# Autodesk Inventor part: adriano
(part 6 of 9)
sketch "スケッチ151"
  geometry: L1 (25.154, 31.686)-(59.588, 31.686) reference; L2 (11.954, 9.686)-(25.154, 31.686) reference; L3 (12.588, 9.686)-(12.588, -19.314) reference; L4 (55.588, -38.314)-(55.588, -23.314) reference; L5 (113.588, -38.314)-(55.588, -38.314) reference; L6 (82.588, 31.686)-(112.588, 31.686) reference; L7 (59.088, -12.814)-(28.088, -12.814) reference; L8 (28.088, -12.814)-(28.088, 12.186) reference; L9 (28.088, 12.186)-(59.088, 12.186) reference; L10 (59.088, 12.186)-(59.088, 25.686) reference; L11 (103.588, 31.686)-(103.588, 2.186); L12 (103.588, 2.186)-(99.588, 2.186); L13 (89.588, 12.186)-(89.588, 24.869); L14 (89.588, 24.869)-(81.529, 24.869); L15 (83.588, 31.686)-(103.588, 31.686); L16 (103.588, -38.314)-(103.588, -1.814); L17 (103.588, -1.814)-(99.588, -1.814); L18 (89.588, -11.814)-(89.588, -26.444); L19 (89.588, -26.444)-(58.713, -26.444); L20 (58.713, -26.444)-(58.713, -14.154); L21 (58.713, -14.154)-(26.588, -14.154); L22 (26.588, -14.154)-(26.588, -8.314); L23 (26.588, -8.314)-(12.588, -8.314); L24 (12.588, -8.314)-(12.588, -23.314); L25 (12.588, -23.314)-(55.588, -23.314); L26 (55.588, -23.314)-(55.588, -38.314); L27 (55.588, -38.314)-(103.588, -38.314); L28 (12.588, -2.229)-(26.588, -2.229); L29 (26.588, -2.229)-(26.588, 13.103); L30 (26.588, 13.103)-(58.238, 13.103); L31 (58.238, 13.103)-(58.238, 31.686); L32 (58.238, 31.686)-(25.154, 31.686); L33 (25.154, 31.686)-(12.588, 10.743); L34 (12.588, 10.743)-(12.588, -2.229); L35 (103.588, 31.686)-(83.588, 31.686); L36 (83.588, 31.686)-(83.588, 24.869); L37 (113.588, -18.314)-(113.588, -38.314) reference; A1 r 10 centre (89.588, 2.186) between (99.588, 2.186) and (89.588, 12.186); A2 r 10 centre (89.588, -1.814) between (89.588, -11.814) and (99.588, -1.814); 1 further point
  constraints: 52 end point, 19 perpendicular, 7 point on line, 4 parallel, 4 point on circle, 2 centre point, 1 collinear
  dimensions: "d2968" = 4 distance between parallel lines of L17 L12; "d2970" = 14 distance between parallel lines of L11 L13; "d2971" = 0 distance between parallel lines of L16 L11; "d2972" = 4 distance of L11.end L12.end; "d2974" = 0 horizontal distance of L17.end L12.end; "d2975" = 0 distance from line of L13 A1.centre; "d2976" = 0 distance from line of L18 A2.centre; "d2977" = 0 distance between parallel lines of L18 L13; "d2978" = 0 distance from line of L17 A2.centre; "d2979" = 29.5 distance between parallel lines of L6 L12; "d2980" = 0 distance between parallel lines of L22 L29; "d2981" = 0 distance from line of L1 L31.end; "d2982" = 14 distance between parallel lines of L22 L3; "d4362" = 10 distance between parallel lines of L37 L16
extrude "garden" join sketch "スケッチ151" distance "d2983" = 0.5; taper "d2984" = 0 deg
sketch "スケッチ158"
  geometry: L1 (-16.412, -4.314)-(-2.412, -4.314) reference; L2 (7.588, -8.314)-(6.588, -8.314) reference; L3 (7.588, -2.314)-(7.588, 9.686) reference; L4 (-19.412, 9.686)-(7.588, 9.686) reference; L5 (-19.412, -18.314)-(-19.412, 9.686) reference; L6 (7.588, -18.314)-(-19.412, -18.314) reference; L7 (-12.588, 9.686)-(7.588, 9.686); L8 (7.588, 9.686)-(7.588, 7.686); L9 (7.588, 7.686)-(-12.588, 7.686); L10 (-12.588, 7.686)-(-12.588, 9.686); L11 (-19.412, 4.686)-(0, 4.686); L12 (0, 4.686)-(0, 1.686); L13 (0, 1.686)-(-19.412, 1.686); L14 (-19.412, 1.686)-(-19.412, 4.686); L15 (0, 4.686)-(2, 4.686); L16 (2, 4.686)-(2, -4.314); L17 (2, -4.314)-(0, -4.314); L18 (0, -4.314)-(0, 4.686); L19 (-19.412, -16.314)-(7.588, -16.314); L20 (7.588, -16.314)-(7.588, -18.314); L21 (7.588, -18.314)-(-19.412, -18.314); L22 (-19.412, -18.314)-(-19.412, -16.314); L23 (0, -8.314)-(7.588, -8.314); L24 (7.588, -8.314)-(7.588, -16.314); L25 (7.588, -16.314)-(0, -16.314); L26 (0, -16.314)-(0, -8.314); C1 r 1 at (5.588, -14.314) reference; 1 further point
  constraints: 40 end point, 10 parallel, 5 horizontal, 5 perpendicular, 4 point on line
  dimensions: "d3045" = 2 distance of L11.end L15.end; "d3047" = 2 distance of L9.end L7.start; "d3048" = 3 distance between parallel lines of L11 L9; "d3049" = 3 distance between parallel lines of L13 L11; "d3050" = 0 distance between parallel lines of L17 L1; "d3051" = 2 distance between parallel lines of L6 L19; "d3052" = 0 distance between parallel lines of L2 L23
extrude "押し出し148" join sketch "スケッチ158" distance "d3053" = 0.5; taper "d3054" = 0 deg
sketch "スケッチ159"
  geometry: L1 (0, 0)-(21, 0) reference; L2 (-0.5, 0)-(9.75, 0); L3 (9.75, 0)-(9.75, 20); L4 (9.75, 20)-(-0.5, 0); L5 (21.5, 0)-(9.75, 0); L6 (9.75, 0)-(9.75, 20); L7 (9.75, 20)-(21.5, 0); 1 further point
  constraints: 12 end point, 2 perpendicular, 2 point on line
  dimensions: "d3055" = 0 distance of L6.end L3.end; "d3057" = 0 distance of L3.end L6.end; "d3058" = 0.5 distance of L5.start L1.end; "d3059" = 0.5 distance of L1.start L2.start; "d3060" = 20 distance of L2.end L3.end
extrude "redroof" join sketch "スケッチ159" distance "d3061" = 48.5; taper "d3062" = 0 deg
sketch "スケッチ160"
  geometry: L1 (-9.75, 20)-(0.5, 0) reference; L2 (0, 0)-(-21, 0) reference; L3 (-21.5, 0)-(-9.75, 20); L4 (-9.75, 20)-(0.5, 0); L5 (0.5, 0)-(-21.5, 0); 1 further point
  constraints: 6 end point, 2 collinear
extrude "押し出し150" join sketch "スケッチ160" distance "d3063" = 0.5; taper "d3064" = 0 deg
sketch "スケッチ161"
  geometry: L1 (0, 0)-(22, 0) reference; L2 (-0.1, 0)-(10.5, 0); L3 (11, 0)-(11, 20); L4 (11, 20)-(-0.1, 0); L5 (22.1, 0)-(11, 0); L6 (11, 0)-(11, 20); L7 (11, 20)-(22.1, 0); 3 further points
  constraints: 12 end point, 2 midpoint, 2 perpendicular, 1 point on line
  dimensions: "d3065" = 0 distance of L6.end L3.end; "d3067" = 1.9 distance of point (-2, 0) L2.start; "d3068" = 1.9 distance of point (24, 0) L5.start; "d3069" = 20 distance from line of L1 L3.end
extrude "押し出し151" join sketch "スケッチ161" distance "d3070" = 52; taper "d3071" = 0 deg
sketch "スケッチ162"
  geometry: L1 (-11, 20)-(0.1, 0) reference; L2 (-22.1, 0)-(-11, 20) reference; L3 (0, 0)-(-22, 0) reference; L4 (-11, 20)-(-22.1, 0); L5 (-22.1, 0)-(0.1, 0); L6 (0.1, 0)-(-11, 20); 1 further point
  constraints: 6 end point, 3 collinear
extrude "押し出し152" join sketch "スケッチ162" distance "d3072" = 0.5; taper "d3073" = 0 deg
sketch "スケッチ163"
  geometry: L1 (0, 0)-(52, 0) reference; L2 (18, -1.6)-(18, -17.464) reference; L3 (34, -17.464)-(34, -1.6) reference; L4 (15.5, 0)-(36.5, 0); L5 (36.5, 0)-(36.5, 20); L6 (36.5, 20)-(15.5, 20); L7 (15.5, 20)-(15.5, 0); 1 further point
  constraints: 8 end point, 2 parallel, 1 horizontal, 1 perpendicular, 1 point on line
  dimensions: "d3074" = 2.5 distance between parallel lines of L2 L7; "d3075" = 2.5 distance between parallel lines of L5 L3; "d3076" = 20 distance between parallel lines of L1 L6
extrude "押し出し153" join sketch "スケッチ163" distance "d3077" = 2; taper "d3078" = 0 deg
sketch "スケッチ164"
  geometry: L1 (18.5, 17.464)-(18.5, 37.464) reference; L2 (-2.5, 37.464)-(-2.5, 17.464) reference; L3 (-18, 17.464)-(-2.5, 17.464) reference; L4 (16, 0)-(16, 15.864) reference; L5 (1.883, 32.964)-(3.483, 32.964); L6 (14.117, 32.964)-(12.517, 32.964); L7 (18.576, 18.464)-(29.7, 26.964); L8 (29.7, 26.964)-(15.7, 26.964); L9 (-2.576, 18.464)-(-13.7, 26.964); L10 (-13.7, 26.964)-(0.3, 26.964); L11 (0.3, 26.964)-(-13.7, 26.964); L12 (-13.7, 26.964)-(-2.7, 30.964); L13 (-2.7, 30.964)-(1.883, 32.964); L14 (18.7, 30.964)-(14.117, 32.964); L15 (18.7, 30.964)-(29.7, 26.964); L16 (29.7, 26.964)-(15.7, 26.964); L17 (-2.7, 30.964)-(-2.7, 38.962); L18 (-2.7, 38.962)-(1.883, 32.964); L19 (14.117, 32.964)-(18.7, 38.962); L20 (18.7, 38.962)-(18.7, 30.964); L21 (-2.7, 38.962)-(18.7, 38.962); L22 (-2.7, 38.962)-(1.883, 32.964); L23 (1.883, 32.964)-(3.483, 32.964); L24 (12.517, 32.964)-(14.117, 32.964); L25 (14.117, 32.964)-(18.7, 38.962); A1 r 14 centre (-13.7, 26.964) between (-2.576, 18.464) and (0.3, 26.964); A2 r 14 centre (29.7, 26.964) between (15.7, 26.964) and (18.576, 18.464); A3 r 5 centre (-2.7, 30.964) between (0.3, 26.964) and (1.883, 32.964); A4 r 5 centre (18.7, 30.964) between (14.117, 32.964) and (15.7, 26.964); A5 r 4.517 centre (8, 32.964) between (12.517, 32.964) and (3.483, 32.964); 1 further point
  constraints: 42 end point, 11 point on circle, 5 centre point, 5 collinear, 3 perpendicular, 2 parallel
  dimensions: "d3085" = 14 distance of L10.end L9.end; "d3087" = 14 distance of L7.end L8.end; "d3088" = 2.8 distance from line of L10.end L2; "d3089" = 2.8 distance from line of L1 L8.end; "d3090" = 11 horizontal distance of L12.end L9.end; "d3091" = 11 horizontal distance of L7.end L14.start; "d3092" = 9.5 distance from line of L3 L9.end; "d3093" = 0 vertical distance of L7.end L9.end; "d3094" = 0 vertical distance of L14.start L12.end; "d3095" = 0 vertical distance of L10.end L9.end; "d3096" = 0 vertical distance of L7.end L8.end; "d3097" = 4 vertical distance of L10.end L12.end; "d3098" = 1 distance from line of L3 L9.start; "d3099" = 0 vertical distance of L7.start L9.start; "d3100" = 1.6 distance of L5.start L5.end; "d3101" = 1.6 distance of L6.start L6.end; "d3102" = 0 distance of L6.end L24.start; "d3103" = 2 distance from line of L12.end L5; "d3104" = 0 distance between parallel lines of L6 L5; "d3105" = 0 distance from line of L6 A5.centre
extrude "押し出し154" cut sketch "スケッチ164" distance "d3106" = 2; taper "d3107" = 0 deg
sketch "スケッチ165"
  geometry: L1 (3.483, 32.964)-(1.883, 32.964) reference; L2 (-2.5, 18.564)-(-2.5, 17.464) reference; L3 (-18, 15.864)-(0, 15.864) reference; L4 (16, 15.864)-(34, 15.864) reference; L5 (14.117, 32.964)-(12.517, 32.964) reference; L6 (8.396, 37.464)-(7.604, 37.464) reference; L7 (2.885, 32.164)-(4.2, 32.164); L8 (4.2, 32.164)-(4.2, 32.964); L9 (11.8, 32.164)-(11.8, 32.964); L10 (-1.7, 18.564)-(-1.7, 15.864); L11 (-1.7, 15.864)-(-2.5, 15.864); L12 (-2.5, 15.864)-(-2.5, 18.564); L13 (17.7, 18.564)-(17.7, 15.864); L14 (17.7, 15.864)-(18.5, 15.864); L15 (18.5, 15.864)-(18.5, 18.564); L16 (1.883, 32.964)-(3.483, 32.964); L17 (12.517, 32.964)-(14.117, 32.964); L18 (-2.5, 18.564)-(-1.7, 18.564); L19 (17.7, 18.564)-(18.5, 18.564); L20 (0.3, 26.964)-(0.942, 26.564); L21 (2.885, 32.164)-(1.883, 32.964); L22 (11.8, 32.164)-(13.123, 32.164); A1 r 4.517 centre (8, 32.964) between (7.604, 37.464) and (3.483, 32.964) reference; A2 r 5 centre (-2.7, 30.964) between (0.3, 26.964) and (1.883, 32.964) reference; A3 r 14 centre (-13.7, 26.964) between (-2.5, 18.564) and (0.3, 26.964) reference; A4 r 14 centre (29.7, 26.964) between (15.7, 26.964) and (18.5, 18.564) reference; A5 r 5 centre (18.7, 30.964) between (14.117, 32.964) and (15.7, 26.964) reference; A6 r 4.517 centre (8, 32.964) between (12.517, 32.964) and (8.396, 37.464) reference; A7 r 14 centre (-13.7, 26.964) between (-2.5, 18.564) and (0.3, 26.964); A8 r 5 centre (-2.7, 30.964) between (0.3, 26.964) and (1.883, 32.964); A9 r 5 centre (18.7, 30.964) between (14.117, 32.964) and (15.7, 26.964); A10 r 14 centre (29.7, 26.964) between (15.7, 26.964) and (18.5, 18.564); A11 r 4.517 centre (8, 32.964) between (12.517, 32.964) and (3.483, 32.964); A12 r 3.8 centre (8, 32.964) between (11.8, 32.964) and (4.2, 32.964); A13 r 5.712 centre (-2.7, 30.964) between (0.942, 26.564) and (2.885, 32.164); A14 r 14.648 centre (-13.7, 26.964) between (-1.7, 18.564) and (0.942, 26.564); A15 r 14.648 centre (29.7, 26.964) between (15.057, 26.574) and (17.7, 18.564); A16 r 5.705 centre (18.7, 30.964) between (13.123, 32.164) and (15.057, 26.574); 1 further point
  constraints: 32 end point, 20 point on circle, 10 centre point, 10 coincident, 6 perpendicular, 5 point on line, 3 parallel, 2 tangent, 1 collinear
  dimensions: "d3110" = 0 vertical distance of L13.start L10.start; "d3111" = 0 vertical distance of L9.start L7.end; "d3112" = 0.8 distance between parallel lines of L10 L12; "d3113" = 0.8 distance between parallel lines of L15 L13; "d3117" = 8 distance from line of L18 L20.end; "d3118" = 5.6 distance from line of L20.end L7; "d3119" = 7.6 distance between parallel lines of L9 L8
extrude "押し出し155" join sketch "スケッチ165" distance "d3122" = 0.5; taper "d3123" = 0 deg
sketch "スケッチ166"
  geometry: L1 (0, 15.864)-(0, 0) reference; L2 (0, 0)-(-18, 0) reference; L3 (0, -1.6)-(0, -16.536) reference; L4 (16, -16.536)-(0, -16.536) reference; L5 (16, -16.536)-(16, -1.6) reference; L6 (16, 0)-(16, 15.864) reference; L7 (16, 15.864)-(17.7, 15.864) reference; L8 (6, 24.464)-(6, 18.464); L9 (6, 18.464)-(10, 18.464); L10 (10, 18.464)-(10, 24.464); L11 (5, 11)-(5, 2); L12 (5, 2)-(11, 2); L13 (11, 2)-(11, 11); L14 (3, -7.536)-(3, -16.536); L15 (3, -16.536)-(13, -16.536); L16 (13, -16.536)-(13, -7.536); L17 (-18, 17.464)-(-2.5, 17.464) reference; C1 r 2.024 at (8, 32.964); A1 r 3.8 centre (8, 32.964) between (11.8, 32.964) and (4.2, 32.964) reference; A2 r 2 centre (8, 24.464) between (8, 26.464) and (6, 24.464); A3 r 2 centre (8, 24.464) between (10, 24.464) and (8, 26.464); A4 r 3 centre (8, 11) between (11, 11) and (5, 11); A5 r 5 centre (8, -7.536) between (13, -7.536) and (3, -7.536); 1 further point
  constraints: 18 end point, 8 point on circle, 5 centre point, 5 perpendicular, 4 parallel, 4 tangent, 2 coincident
  dimensions: "d3126" = 3 distance between parallel lines of L3 L14; "d3127" = 3 distance between parallel lines of L5 L16; "d3128" = 0 distance between parallel lines of L4 L15; "d3129" = 9 distance from line of L15 A5.centre; "d3130" = 2 distance between parallel lines of L2 L12; "d3131" = 5 distance between parallel lines of L1 L11; "d3132" = 5 distance between parallel lines of L6 L13; "d3133" = 9 distance from line of L12 A4.centre; "d3134" = 0 vertical distance of L13.end A4.centre; "d3135" = 1 distance between parallel lines of L17 L9; "d3136" = 6 distance from line of L9 A3.centre; "d3137" = 6 distance between parallel lines of L1 L8; "d3138" = 6 distance between parallel lines of L6 L10; "d3139" = 4 distance of L8.end L9.end (derived)
extrude "押し出し156" cut sketch "スケッチ166" distance "d3140" = 0.5; taper "d3141" = 0 deg
sketch "スケッチ167"
  geometry: L1 (0, 1.6)-(15.5, 1.6) reference; L2 (0, 0)-(15.5, 0) reference; L3 (1.5, 1.6)-(1.5, 21.6); L4 (1.5, 21.6)-(12.5, 21.6); L5 (1.5, 1.6)-(12.5, 21.6); L6 (39.5, 21.6)-(50.5, 21.6); L7 (50.5, 21.6)-(50.5, 1.929); L8 (50.5, 1.929)-(39.5, 21.6); L9 (1.5, 1.6)-(1.5, 21.6) reference; L10 (50.5, 21.6)-(50.5, 1.6) reference; L11 (1.5, 21.6)-(26, 21.6) reference; 1 further point
  constraints: 12 end point, 3 perpendicular, 1 collinear
  dimensions: "d3142" = 11 distance of L3.end L4.end; "d3144" = 11 distance of L6.start L6.end; "d3145" = 0 distance between parallel lines of L9 L3; "d3146" = 0 distance between parallel lines of L10 L7; "d3147" = 0 distance from line of L1 L3.start; "d3148" = 0 distance between parallel lines of L11 L4; "d3149" = 0 distance between parallel lines of L6 L4
extrude "押し出し157" cut sketch "スケッチ167" distance "d3150" = 28; taper "d3151" = 0 deg
sketch "スケッチ168"
  geometry: L1 (0, 0)-(31, 0) reference; L2 (0, -1.6)-(0, 0) reference; L3 (1.5, 0)-(1.5, 20); L4 (1.5, 20)-(12.5, 20); L5 (12.5, 20)-(1.5, 0); L6 (1.5, 0)-(1.5, 20) reference; L7 (1.5, 20)-(44.25, 20) reference; 1 further point
  constraints: 6 end point, 1 parallel, 1 perpendicular, 1 point on line
  dimensions: "d3152" = 11 distance of L3.end L4.end; "d3156" = 0 distance between parallel lines of L6 L3; "d3157" = 0 distance between parallel lines of L7 L4
extrude "押し出し158" cut sketch "スケッチ168" distance "d3154" = 28; taper "d3155" = 0 deg
sketch "スケッチ169"
  geometry: L1 (60.088, -11.414)-(29.088, -11.414) reference; L2 (29.088, 10.786)-(60.088, 10.786) reference; L3 (60.088, 10.786)-(60.088, 24.186) reference; L4 (69.588, 1.786)-(73.788, 1.786); L5 (73.788, 1.786)-(73.788, -2.414); L6 (73.788, -2.414)-(69.588, -2.414); L7 (69.588, -2.414)-(69.588, 1.786); 1 further point
  constraints: 8 end point, 2 parallel, 1 horizontal, 1 perpendicular
  dimensions: "d3158" = 9 distance between parallel lines of L2 L4; "d3159" = 9 distance between parallel lines of L1 L6; "d3162" = 4.2 distance of L4.start L4.end; "d3163" = 9.5 distance between parallel lines of L7 L3
extrude "top" join sketch "スケッチ169" distance "d3164" = 21; taper "d3165" = 0 deg
sketch "スケッチ170"
  geometry: L1 (73.788, 1.786)-(69.588, 1.786) reference; L2 (69.588, 1.786)-(69.588, -2.414) reference; L3 (69.588, -2.414)-(73.788, -2.414) reference; L4 (73.788, -2.414)-(73.788, 1.786) reference; L5 (70.388, 0.986)-(70.388, -1.614); L6 (70.388, -1.614)-(72.988, -1.614); L7 (72.988, -1.614)-(72.988, 0.986); L8 (72.988, 0.986)-(70.388, 0.986); L9 (70.988, 0.386)-(70.988, -1.014); L10 (70.988, -1.014)-(72.388, -1.014); L11 (72.388, -1.014)-(72.388, 0.386); L12 (72.388, 0.386)-(70.988, 0.386); 1 further point
  constraints: 16 end point, 4 parallel, 4 perpendicular
  dimensions: "d3166" = 0.8 distance between parallel lines of L2 L5; "d3167" = 0.8 distance between parallel lines of L4 L7; "d3168" = 0.8 distance between parallel lines of L1 L8; "d3169" = 0.8 distance between parallel lines of L3 L6; "d3170" = 0.6 distance between parallel lines of L6 L10; "d3171" = 0.6 distance between parallel lines of L8 L12; "d3172" = 0.6 distance between parallel lines of L5 L9; "d3173" = 0.6 distance between parallel lines of L7 L11
extrude "押し出し160" join sketch "スケッチ170" distance "d3174" = 4; taper "d3175" = 0 deg
sketch "スケッチ171"
  geometry: L1 (2.6, 0)-(0, 0) reference; L2 (2.6, 0)-(2.6, 4) reference; L3 (0, 4)-(2.6, 4) reference; L4 (0, 0)-(0, 4) reference; L5 (0.8, 2.6)-(1.8, 2.6); L6 (1.8, 2.6)-(1.8, 1); L7 (1.8, 1)-(0.8, 1); L8 (0.8, 1)-(0.8, 2.6); 1 further point
  constraints: 8 end point, 2 parallel, 1 horizontal, 1 perpendicular
  dimensions: "d3176" = 1 distance between parallel lines of L1 L7; "d3177" = 1.4 distance between parallel lines of L5 L3; "d3178" = 0.8 distance between parallel lines of L4 L8; "d3179" = 0.8 distance between parallel lines of L2 L6
extrude "押し出し161" cut sketch "スケッチ171" distance "d3180" = 10; taper "d3181" = 0 deg
sketch "スケッチ172"
  geometry: L1 (2.6, 0)-(0, 0) reference; L2 (2.6, 0)-(2.6, 4) reference; L3 (0, 4)-(2.6, 4) reference; L4 (0, 0)-(0, 4) reference; L5 (0.8, 2.6)-(1.8, 2.6); L6 (1.8, 2.6)-(1.8, 1); L7 (1.8, 1)-(0.8, 1); L8 (0.8, 1)-(0.8, 2.6); 1 further point
  constraints: 8 end point, 2 parallel, 1 horizontal, 1 perpendicular
  dimensions: "d3182" = 0.8 distance between parallel lines of L4 L8; "d3183" = 0.8 distance between parallel lines of L2 L6; "d3184" = 1.4 distance between parallel lines of L5 L3; "d3185" = 1 distance between parallel lines of L1 L7
extrude "押し出し162" cut sketch "スケッチ172" distance "d3186" = 6; taper "d3187" = 0 deg
sketch "スケッチ173"
  geometry: L1 (70.988, -1.014)-(70.988, 0.386) reference; L2 (70.988, 0.386)-(72.388, 0.386) reference; C1 r 2.3 at (71.688, -0.314); 1 further point
  constraints: 1 centre point
  dimensions: "d3188" = 4.6 diameter of C1; "d3190" = 0.7 distance from line of L1 C1.centre; "d4361" = 0.7 distance from line of L2 C1.centre
extrude "押し出し163" join sketch "スケッチ173" distance "d3191" = 0.5; taper "d3192" = 0 deg
sketch "スケッチ174"
  geometry: C1 r 2.3 at (0, 0) reference; C2 r 0.5 at (0, 0); 1 further point
  constraints: 1 centre point, 1 coincident
  dimensions: "d3193" = 1 diameter of C2
extrude "押し出し164" join sketch "スケッチ174" distance "d3196" = 3; taper "d3197" = 0 deg
sketch "スケッチ175"
  geometry: L1 (-1.6, 1.6)-(1.6, 1.6); L2 (1.6, 1.6)-(1.6, -1.6); L3 (1.6, -1.6)-(-1.6, -1.6); L4 (-1.6, -1.6)-(-1.6, 1.6); L5 (2.1, 2.1)-(-2.1, 2.1) reference; L6 (-2.1, -2.1)-(2.1, -2.1) reference; L7 (-2.1, 2.1)-(-2.1, -2.1) reference; L8 (2.1, -2.1)-(2.1, 2.1) reference; C1 r 0.5 at (0, 0) reference; 1 further point
  constraints: 8 end point, 2 parallel, 1 horizontal, 1 perpendicular
  dimensions: "d3198" = 0.5 distance between parallel lines of L5 L1; "d3199" = 0.5 distance between parallel lines of L6 L3; "d3200" = 0.5 distance between parallel lines of L7 L4; "d3201" = 0.5 distance between parallel lines of L8 L2
extrude "押し出し165" join sketch "スケッチ175" distance "d3202" = 2; taper "d3203" = 0 deg
fillet "フィレット3" dims "d3204" = 1.2
fillet "フィレット4" dims "d3205" = 1.2
sketch "スケッチ176"
  geometry: C1 r 0.5 at (0, 0) reference; C2 r 0.3 at (0, 0); 1 further point
  constraints: 1 centre point, 1 coincident
  dimensions: "d3206" = 0.6 diameter of C2
extrude "押し出し166" join sketch "スケッチ176" distance "d3208" = 2; taper "d3209" = 0 deg
sketch "スケッチ178"
  geometry: L1 (0, 0)-(15.5, 0) reference; L2 (9.5, 8.6)-(9.5, 2.6); L3 (9.5, 2.6)-(14.5, 2.6); L4 (14.5, 2.6)-(14.5, 8.6); L5 (37.5, 8.6)-(37.5, 2.6); L6 (37.5, 2.6)-(42.5, 2.6); L7 (42.5, 2.6)-(42.5, 8.6); L8 (15.5, 2.7)-(15.5, 0) reference; L9 (36.5, 0)-(36.5, 2.7) reference; L10 (36.5, 1.6)-(52, 1.6) reference; A1 r 2.5 centre (12, 8.6) between (14.5, 8.6) and (9.5, 8.6); A2 r 2.5 centre (40, 8.6) between (42.5, 8.6) and (37.5, 8.6); 1 further point
  constraints: 12 end point, 4 point on circle, 3 parallel, 3 perpendicular, 2 centre point
  dimensions: "d3225" = 5 distance of L2.end L3.end; "d3227" = 5 distance of L5.end L6.end; "d3228" = 1 distance between parallel lines of L8 L4; "d3229" = 1 distance between parallel lines of L5 L9; "d3230" = 180 deg dimension on A2.centre L7.end L5.start; "d3231" = 0 vertical distance of L7.end L5.start; "d3232" = 1 distance between parallel lines of L10 L6; "d3233" = 0 distance between parallel lines of L6 L3; "d3234" = 0 vertical distance of L4.end L2.start; "d3235" = 0 vertical distance of L2.start A1.centre; "d3236" = 0 vertical distance of A2.centre A1.centre; "d3237" = 6 distance of L6.end L7.end
extrude "押し出し168" join sketch "スケッチ178" distance "d3238" = 10; taper "d3239" = 0 deg
sketch "スケッチ179"
  geometry: L1 (9.5, 8.6)-(9.5, 2.6) reference; L2 (9.5, 2.6)-(14.5, 2.6) reference; L3 (14.5, 2.6)-(14.5, 8.6) reference; L4 (9.5, 8.6)-(9.5, 2.6); L5 (9.5, 2.6)-(14.5, 2.6); L6 (14.5, 2.6)-(14.5, 8.6); L7 (37.5, 8.6)-(37.5, 2.6); L8 (37.5, 2.6)-(42.5, 2.6); L9 (42.5, 2.6)-(42.5, 8.6); L10 (37.5, 8.6)-(37.5, 2.6) reference; L11 (37.5, 2.6)-(42.5, 2.6) reference; A1 r 2.5 centre (12, 8.6) between (14.5, 8.6) and (9.5, 8.6) reference; A2 r 2.5 centre (12, 8.6) between (14.5, 8.6) and (9.5, 8.6); A3 r 2.5 centre (40, 8.65) between (42.5, 8.6) and (37.5, 8.6); 1 further point
  constraints: 12 end point, 5 equal length, 4 point on circle, 2 centre point, 2 tangent, 1 coincident, 1 perpendicular
  dimensions: "d3242" = 0 distance between parallel lines of L10 L7; "d3243" = 6 distance of L8.end L9.end; "d3244" = 0 distance between parallel lines of L8 L11; "d3245" = 5 distance of L7.end L8.end
extrude "押し出し169" cut sketch "スケッチ179" distance "d3240" = 1; taper "d3241" = 0 deg
sketch "スケッチ180"
  geometry: L1 (42.5, 8.6)-(42.5, 2.6) reference; L2 (9, 8.6)-(9.5, 8.6); L3 (14.5, 8.6)-(15, 8.6); L4 (37, 8.6)-(37.5, 8.6); L5 (42.5, 8.6)-(43, 8.6); L6 (9.5, 2.6)-(9.5, 8.6) reference; L7 (14.5, 2.6)-(9.5, 2.6) reference; A1 r 2.5 centre (40, 8.6) between (42.5, 8.6) and (37.5, 8.6) reference; A2 r 3 centre (40, 8.6) between (43, 8.6) and (37, 8.6); A3 r 2.5 centre (40, 8.6) between (42.5, 8.6) and (37.5, 8.6); A4 r 2.5 centre (12, 8.6) between (14.5, 8.6) and (9.5, 8.6); A5 r 3 centre (12, 8.6) between (15, 8.6) and (9, 8.6); 1 further point
  constraints: 8 end point, 8 point on circle, 4 centre point, 3 coincident, 3 collinear, 1 perpendicular
  dimensions: "d3246" = 0.5 distance of L4.start L4.end; "d3247" = 0.5 distance of L2.start L2.end; "d3248" = 2.5 distance of L3.start A4.centre; "d3249" = 0 distance from line of L6 L2.end; "d3250" = 0 distance between parallel lines of L3 L2; "d3251" = 0 distance from line of L3 A4.centre; "d3252" = 6 distance from line of L7 A4.centre
extrude "押し出し170" join sketch "スケッチ180" distance "d3253" = 10; taper "d3254" = 0 deg
sketch "スケッチ181"
  geometry: L1 (9.5, 2.6)-(9.5, 8.6) reference; L2 (14.5, 8.6)-(14.5, 2.6) reference; L3 (9.5, 8.6)-(9.5, 2.6); L4 (9.5, 2.6)-(14.5, 2.6); L5 (14.5, 2.6)-(14.5, 8.6); A1 r 3 centre (12, 8.6) between (15, 8.6) and (9, 8.6) reference; A2 r 2.5 centre (12, 8.6) between (14.5, 8.6) and (9.5, 8.6); 1 further point
  constraints: 6 end point, 2 collinear, 2 point on circle, 2 tangent, 1 centre point, 1 coincident, 1 perpendicular
extrude "押し出し171" cut sketch "スケッチ181" distance "d3255" = 0.5; taper "d3256" = 0 deg
sketch "スケッチ182"
  geometry: L1 (37.5, 2.6)-(37.5, 8.6) reference; L2 (37, 8.6)-(37.5, 8.6) reference; L3 (37.5, 8.6)-(37.5, 2.6); L4 (37.5, 2.6)-(42.5, 2.6); L5 (42.5, 2.6)-(42.5, 8.6); A1 r 3 centre (40, 8.6) between (43, 8.6) and (37, 8.6) reference; A2 r 2.5 centre (40, 8.6) between (42.5, 8.6) and (37.5, 8.6); 1 further point
  constraints: 6 end point, 3 perpendicular, 2 point on circle, 2 tangent, 1 centre point, 1 coincident
extrude "押し出し172" cut sketch "スケッチ182" distance "d3257" = 0.5; taper "d3258" = 0 deg
sketch "スケッチ183"
  geometry: L1 (0, 0)-(25, 0) reference; L2 (0, -1.6)-(0, 0) reference; L3 (9.5, 7)-(9.5, 1); L4 (9.5, 1)-(14.5, 1); L5 (14.5, 1)-(14.5, 7); A1 r 2.5 centre (12, 7) between (14.5, 7) and (9.5, 7); 1 further point
  constraints: 6 end point, 2 parallel, 2 point on circle, 1 centre point, 1 perpendicular
  dimensions: "d3259" = 1 distance between parallel lines of L1 L4; "d3260" = 5 distance of L3.end L4.end; "d3261" = 0 vertical distance of L5.end A1.centre; "d3262" = 6 distance from line of L4 A1.centre; "d3263" = 9.5 distance between parallel lines of L2 L3; "d3264" = 0 vertical distance of A1.centre L3.start
extrude "押し出し173" join sketch "スケッチ183" distance "d3265" = 50.5; taper "d3266" = 0 deg
sketch "スケッチ184"
  geometry: L1 (9.5, 7)-(9.5, 1) reference; L2 (14.5, 1)-(14.5, 7) reference; L3 (9.5, 7)-(9.5, 1); L4 (9.5, 1)-(14.5, 1); L5 (14.5, 1)-(14.5, 7); A1 r 2.5 centre (12, 7) between (14.5, 7) and (9.5, 7) reference; A2 r 2.5 centre (12, 7) between (14.5, 7) and (9.5, 7); 1 further point
  constraints: 6 end point, 2 equal length, 2 point on circle, 2 tangent, 1 centre point, 1 coincident, 1 perpendicular
extrude "押し出し174" cut sketch "スケッチ184" distance "d3267" = 0.5; taper "d3268" = 0 deg
sketch "スケッチ185"
  geometry: L1 (14.5, 7)-(14.5, 1) reference; L2 (9, 7)-(9.5, 7); L3 (14.5, 7)-(15, 7); A1 r 2.5 centre (12, 7) between (14.5, 7) and (9.5, 7) reference; A2 r 3 centre (12, 7) between (15, 7) and (9, 7); A3 r 2.5 centre (12, 7) between (14.5, 7) and (9.5, 7); 1 further point
  constraints: 4 end point, 4 point on circle, 2 centre point, 2 coincident, 1 collinear, 1 perpendicular
  dimensions: "d3269" = 0.5 distance of L2.start L2.end
extrude "押し出し175" join sketch "スケッチ185" distance "d3270" = 51; taper "d3271" = 0 deg
sketch "スケッチ186"
  geometry: L1 (9.5, 1)-(9.5, 7) reference; L2 (9, 7)-(9.5, 7) reference; L3 (9.5, 7)-(9.5, 1); L4 (9.5, 1)-(14.5, 1); L5 (14.5, 1)-(14.5, 7); A1 r 3 centre (12, 7) between (15, 7) and (9, 7) reference; A2 r 2.5 centre (12, 7) between (14.5, 7) and (9.5, 7); 1 further point
  constraints: 6 end point, 3 perpendicular, 2 point on circle, 2 tangent, 1 centre point, 1 coincident
extrude "押し出し176" cut sketch "スケッチ186" distance "d3272" = 0.5; taper "d3273" = 0 deg
sketch "スケッチ187"
  geometry: L1 (31, -1.6)-(31, 0) reference; L2 (0, 0)-(31, 0) reference; L3 (0, -1.6)-(0, 0) reference; L4 (2, 7)-(2, 1); L5 (2, 1)-(7, 1); L6 (7, 1)-(7, 7); L7 (14, 7)-(14, 1); L8 (14, 1)-(19, 1); L9 (19, 1)-(19, 7); A1 r 2.5 centre (4.5, 7) between (7, 7) and (2, 7); A2 r 2.5 centre (16.5, 7) between (19, 7) and (14, 7); 1 further point
  constraints: 12 end point, 4 parallel, 4 point on circle, 2 centre point, 2 perpendicular
  dimensions: "d3274" = 5 distance of L4.end L5.end; "d3276" = 5 distance of L7.end L8.end; "d3277" = 6 distance from line of L8 A2.centre; "d3278" = 1 distance between parallel lines of L2 L8; "d3279" = 0 distance between parallel lines of L8 L5; "d3280" = 0 vertical distance of A2.centre A1.centre; "d3281" = 7 distance between parallel lines of L7 L6; "d3282" = 12 distance between parallel lines of L9 L1; "d3283" = 0 vertical distance of L9.end A2.centre; "d3284" = 0 vertical distance of A1.centre L6.end; "d3285" = 0 vertical distance of A1.centre L4.start
extrude "押し出し177" join sketch "スケッチ187" distance "d3286" = 24.2; taper "d3287" = 0 deg
sketch "スケッチ188"
  geometry: L1 (2, 7)-(2, 1) reference; L2 (7, 1)-(7, 7) reference; L3 (2, 7)-(2, 1); L4 (2, 1)-(7, 1); L5 (7, 1)-(7, 7); A1 r 2.5 centre (4.5, 7) between (7, 7) and (2, 7) reference; A2 r 2.5 centre (4.5, 7) between (7, 7) and (2, 7); 1 further point
  constraints: 6 end point, 4 tangent, 2 equal length, 2 point on circle, 1 centre point, 1 coincident, 1 perpendicular
extrude "押し出し178" cut sketch "スケッチ188" distance "d3288" = 0.5; taper "d3289" = 0 deg
sketch "スケッチ189"
  geometry: L1 (14, 7)-(14, 1) reference; L2 (19, 1)-(19, 7) reference; L3 (14, 7)-(14, 1); L4 (14, 1)-(19, 1); L5 (19, 1)-(19, 7); A1 r 2.5 centre (16.5, 7) between (19, 7) and (14, 7) reference; A2 r 2.5 centre (16.5, 7) between (19, 7) and (14, 7); 1 further point
  constraints: 6 end point, 4 tangent, 2 equal length, 2 point on circle, 1 centre point, 1 coincident, 1 perpendicular
extrude "押し出し179" cut sketch "スケッチ189" distance "d3290" = 0.5; taper "d3291" = 0 deg
sketch "スケッチ190"
  geometry: L1 (7, 7)-(7, 1) reference; L2 (1.5, 7)-(2, 7); L3 (7, 7)-(7.5, 7); A1 r 2.5 centre (4.5, 7) between (7, 7) and (2, 7) reference; A2 r 3 centre (4.5, 7) between (7.5, 7) and (1.5, 7); A3 r 2.5 centre (4.5, 7) between (7, 7) and (2, 7); 1 further point
  constraints: 4 end point, 4 point on circle, 2 centre point, 2 coincident, 1 collinear, 1 perpendicular
  dimensions: "d3292" = 0.5 distance of L2.start L2.end
extrude "押し出し180" join sketch "スケッチ190" distance "d3293" = 24.5; taper "d3294" = 0 deg
sketch "スケッチ191"
  geometry: L1 (19, 7)-(19, 1) reference; L2 (13.5, 7)-(14, 7); L3 (19, 7)-(19.5, 7); A1 r 2.5 centre (16.5, 7) between (19, 7) and (14, 7) reference; A2 r 3 centre (16.5, 7) between (19.5, 7) and (13.5, 7); A3 r 2.5 centre (16.5, 7) between (19, 7) and (14, 7); 1 further point
  constraints: 4 end point, 4 point on circle, 2 centre point, 2 coincident, 1 collinear, 1 perpendicular
  dimensions: "d3295" = 0.5 distance of L2.start L2.end
extrude "押し出し181" join sketch "スケッチ191" distance "d3296" = 24.5; taper "d3297" = 0 deg
sketch "スケッチ192"
  geometry: L1 (2, 1)-(2, 7) reference; L2 (7, 7)-(7, 1) reference; L3 (1.5, 7)-(2, 7) reference; L4 (2, 7)-(2, 1); L5 (2, 1)-(7, 1); L6 (7, 1)-(7, 7); A1 r 3 centre (4.5, 7) between (7.5, 7) and (1.5, 7) reference; A2 r 2.5 centre (4.5, 7) between (7, 7) and (2, 7); 1 further point
  constraints: 6 end point, 2 perpendicular, 2 point on circle, 2 tangent, 1 centre point, 1 coincident, 1 collinear
extrude "押し出し182" cut sketch "スケッチ192" distance "d3298" = 0.5; taper "d3299" = 0 deg
sketch "スケッチ193"
  geometry: L1 (14, 1)-(14, 7) reference; L2 (19, 1)-(14, 1) reference; L3 (19, 7)-(19, 1) reference; L4 (13.5, 7)-(14, 7) reference; L5 (14, 7)-(14, 1); L6 (14, 1)-(19, 1); L7 (19, 1)-(19, 7); A1 r 3 centre (16.5, 7) between (19.5, 7) and (13.5, 7) reference; A2 r 2.5 centre (16.5, 7) between (19, 7) and (14, 7); 1 further point
  constraints: 6 end point, 2 collinear, 2 point on circle, 2 tangent, 1 centre point, 1 coincident, 1 perpendicular
extrude "押し出し183" cut sketch "スケッチ193" distance "d3300" = 0.5; taper "d3301" = 0 deg
chamfer "面取り1" distance "d3302" = 0.5; stored, may be unused: second distance "d3303" = 2, angle "d3304" = 45 deg
sketch "スケッチ195"
  geometry: L1 (0, 0)-(4.2, 0) reference; L2 (0, -4.784)-(0, 0) reference; L3 (1.75, -1)-(2.75, -1); L4 (2.75, -1)-(2.75, -1.5); L5 (2.75, -1.5)-(1.75, -1.5); L6 (1.75, -1.5)-(1.75, -1); 1 further point
  constraints: 8 end point, 2 parallel, 1 horizontal, 1 perpendicular
  dimensions: "d3305" = 1 distance of L3.start L3.end; "d3307" = 0.5 distance of L3.end L4.end; "d3308" = 1 distance between parallel lines of L3 L1; "d3309" = 1.75 distance between parallel lines of L2 L6
extrude "押し出し184" join sketch "スケッチ195" distance "d3310" = 12; taper "d3311" = 0 deg
sketch "スケッチ196"
  geometry: L1 (0, 0)-(4.2, 0) reference; L2 (0, -4.784)-(0, 0) reference; L3 (1.7, -1)-(2.7, -1); L4 (2.7, -1)-(2.7, -1.5); L5 (2.7, -1.5)-(1.7, -1.5); L6 (1.7, -1.5)-(1.7, -1); 1 further point
  constraints: 8 end point, 2 parallel, 1 horizontal, 1 perpendicular
  dimensions: "d3312" = 1 distance of L3.start L3.end; "d3314" = 0.5 distance of L3.end L4.end; "d3315" = 1 distance between parallel lines of L3 L1; "d3316" = 1.7 distance between parallel lines of L2 L6
extrude "押し出し185" join sketch "スケッチ196" distance "d3317" = 12; taper "d3318" = 0 deg
sketch "スケッチ197"
  geometry: L1 (-4.2, 4.784)-(0, 4.784) reference; L2 (-4.2, 0)-(-4.2, 4.784) reference; L3 (-2.6, 3.784)-(-1.6, 3.784); L4 (-1.6, 3.784)-(-1.6, 3.284); L5 (-1.6, 3.284)-(-2.6, 3.284); L6 (-2.6, 3.284)-(-2.6, 3.784); 1 further point
  constraints: 8 end point, 2 parallel, 1 horizontal, 1 perpendicular
  dimensions: "d3319" = 1 distance of L3.start L3.end; "d3321" = 0.5 distance of L3.end L4.end; "d3322" = 1 distance between parallel lines of L3 L1; "d3323" = 1.6 distance between parallel lines of L6 L2
extrude "押し出し186" join sketch "スケッチ197" distance "d3324" = 8; taper "d3325" = 0 deg
sketch "スケッチ198"
  geometry: L1 (-4.2, 4.784)-(0, 4.784) reference; L2 (-4.2, 0)-(-4.2, 4.784) reference; L3 (-2.6, 3.784)-(-1.6, 3.784); L4 (-1.6, 3.784)-(-1.6, 3.284); L5 (-1.6, 3.284)-(-2.6, 3.284); L6 (-2.6, 3.284)-(-2.6, 3.784); 1 further point
  constraints: 8 end point, 2 parallel, 1 horizontal, 1 perpendicular
  dimensions: "d3326" = 1 distance of L3.start L3.end; "d3328" = 0.5 distance of L3.end L4.end; "d3329" = 1 distance between parallel lines of L3 L1; "d3330" = 1.6 distance between parallel lines of L6 L2
extrude "押し出し187" join sketch "スケッチ198" distance "d3331" = 30; taper "d3332" = 0 deg
sketch "スケッチ199"
  geometry: L1 (-14.5, 7)-(-14.5, 1) reference; L2 (-14.5, 1)-(-9.5, 1) reference; L3 (-13.25, 6.6)-(-12.25, 6.6); L4 (-12.25, 6.6)-(-12.25, 5.4); L5 (-12.25, 5.4)-(-13.25, 5.4); L6 (-13.25, 5.4)-(-13.25, 6.6); L7 (-11.75, 6.6)-(-10.75, 6.6); L8 (-10.75, 6.6)-(-10.75, 5.4); L9 (-10.75, 5.4)-(-11.75, 5.4); L10 (-11.75, 5.4)-(-11.75, 6.6); L11 (-13.25, 4.9)-(-12.25, 4.9); L12 (-12.25, 4.9)-(-12.25, 3.7); L13 (-12.25, 3.7)-(-13.25, 3.7); L14 (-13.25, 3.7)-(-13.25, 4.9); L15 (-11.75, 4.9)-(-10.75, 4.9); L16 (-10.75, 4.9)-(-10.75, 3.7); L17 (-10.75, 3.7)-(-11.75, 3.7); L18 (-11.75, 3.7)-(-11.75, 4.9); L19 (-13.25, 3.2)-(-12.25, 3.2); L20 (-12.25, 3.2)-(-12.25, 2); L21 (-12.25, 2)-(-13.25, 2); L22 (-13.25, 2)-(-13.25, 3.2); L23 (-11.75, 3.2)-(-10.75, 3.2); L24 (-10.75, 3.2)-(-10.75, 2); L25 (-10.75, 2)-(-11.75, 2); L26 (-11.75, 2)-(-11.75, 3.2); L27 (-28.25, 3.7)-(-29.25, 3.7); L28 (-29.75, 3.7)-(-30.75, 3.7); L29 (-29.25, 3.7)-(-29.25, 4.9); L30 (-29.25, 4.9)-(-28.25, 4.9); L31 (-29.75, 4.9)-(-29.75, 3.7); L32 (-30.75, 4.9)-(-29.75, 4.9); L33 (-28.25, 4.9)-(-28.25, 3.7); L34 (-30.75, 3.7)-(-30.75, 4.9); L35 (-29.25, 3.2)-(-28.25, 3.2); L36 (-30.75, 3.2)-(-29.75, 3.2); L37 (-28.25, 3.2)-(-28.25, 2); L38 (-28.25, 2)-(-29.25, 2); L39 (-29.25, 2)-(-29.25, 3.2); L40 (-29.75, 3.2)-(-29.75, 2); L41 (-30.75, 2)-(-30.75, 3.2); L42 (-29.75, 2)-(-30.75, 2); L43 (-29.75, 5.4)-(-30.75, 5.4); L44 (-28.25, 5.4)-(-29.25, 5.4); L45 (-30.75, 6.614)-(-29.75, 6.614); L46 (-30.75, 5.4)-(-30.75, 6.614); L47 (-28.25, 6.6)-(-28.25, 5.4); L48 (-29.25, 5.4)-(-29.25, 6.6); L49 (-29.75, 6.614)-(-29.75, 5.4); L50 (-29.25, 6.6)-(-28.25, 6.6); L51 (-41.75, 2)-(-42.75, 2); L52 (-40.25, 3.7)-(-41.25, 3.7); L53 (-41.75, 3.7)-(-42.75, 3.7); L54 (-42.75, 4.9)-(-41.75, 4.9); L55 (-41.25, 3.7)-(-41.25, 4.9); L56 (-40.25, 4.9)-(-40.25, 3.7); L57 (-41.75, 4.9)-(-41.75, 3.7); L58 (-42.75, 3.7)-(-42.75, 4.9); L59 (-42.75, 6.6)-(-41.75, 6.6); L60 (-41.75, 6.6)-(-41.75, 5.4); L61 (-41.75, 5.4)-(-42.75, 5.4); L62 (-42.75, 5.4)-(-42.75, 6.6); L63 (-41.25, 6.6)-(-40.25, 6.6); L64 (-40.25, 6.6)-(-40.25, 5.4)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; 3 further points
  constraints: 144 end point, 36 parallel, 18 horizontal, 18 perpendicular
  dimensions: "d3333" = 1 distance of L3.start L3.end; "d3335" = 1 distance of L7.start L7.end; "d3336" = 0.5 distance between parallel lines of L10 L4; "d3337" = 0 distance between parallel lines of L16 L8; "d3338" = 0 distance between parallel lines of L24 L16; "d3339" = 0 distance between parallel lines of L18 L10; "d3340" = 0 distance between parallel lines of L26 L18; "d3341" = 1.2 distance of L7.end L8.end; "d3342" = 0.5 distance between parallel lines of L15 L9; "d3343" = 0.5 distance between parallel lines of L23 L17; "d3344" = 1.2 distance of L15.end L16.end; "d3345" = 1.2 distance of L23.end L24.end; "d3346" = 0 distance between parallel lines of L25 L21; "d3347" = 0 distance between parallel lines of L9 L5; "d3348" = 0 distance between parallel lines of L15 L11; "d3349" = 0 distance between parallel lines of L17 L13; "d3350" = 0 distance between parallel lines of L23 L19; "d3351" = 1 distance between parallel lines of L2 L25; "d3352" = 1.25 distance between parallel lines of L22 L1; "d3353" = 0 distance between parallel lines of L22 L14; "d3354" = 0 distance between parallel lines of L14 L6; "d3355" = 0 distance between parallel lines of L12 L4; "d3356" = 0 distance between parallel lines of L20 L12; "d3357" = 1 distance of L45.start L45.end; "d3358" = 1 distance of L48.end L47.start; "d3359" = 0.5 distance between parallel lines of L48 L49; "d3360" = 0 distance between parallel lines of L33 L47; "d3361" = 0 distance between parallel lines of L37 L33; "d3362" = 0 distance between parallel lines of L29 L48; "d3363" = 0 distance between parallel lines of L39 L29; "d3364" = 1.2 distance of L47.start L44.start; "d3365" = 0.5 distance between parallel lines of L30 L44; "d3366" = 0.5 distance between parallel lines of L35 L27; "d3367" = 1.2 distance of L30.end L27.start; "d3368" = 1.2 distance of L35.end L37.end; "d3369" = 0 distance between parallel lines of L38 L42; "d3370" = 0 distance between parallel lines of L44 L43; "d3371" = 0 distance between parallel lines of L30 L32; "d3372" = 0 distance between parallel lines of L27 L28; "d3373" = 0 distance between parallel lines of L35 L36; "d3374" = 0 distance between parallel lines of L41 L34; "d3375" = 0 distance between parallel lines of L34 L46; "d3376" = 0 distance between parallel lines of L31 L49; "d3377" = 0 distance between parallel lines of L40 L31; "d3378" = 1 distance of L59.start L59.end; "d3379" = 1 distance of L63.start L63.end; "d3380" = 0.5 distance between parallel lines of L67 L60; "d3381" = 0 distance between parallel lines of L56 L64; "d3382" = 0 distance between parallel lines of L74 L56; "d3383" = 0 distance between parallel lines of L55 L67; "d3384" = 0 distance between parallel lines of L71 L55; "d3385" = 1.2 distance of L63.end L64.end; "d3386" = 0.5 distance between parallel lines of L66 L65; "d3387" = 0.5 distance between parallel lines of L73 L52; "d3388" = 1.2 distance of L56.start L52.start; "d3389" = 1.2 distance of L73.end L72.start; "d3390" = 0 distance between parallel lines of L72 L51; "d3391" = 0 distance between parallel lines of L65 L61; "d3392" = 0 distance between parallel lines of L66 L54; "d3393" = 0 distance between parallel lines of L52 L53; "d3394" = 0 distance between parallel lines of L73 L68; "d3397" = 0 distance between parallel lines of L69 L58; "d3398" = 0 distance between parallel lines of L58 L62; "d3399" = 0 distance between parallel lines of L57 L60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
extrude "押し出し188" cut sketch "スケッチ199" distance "d3406" = 50; taper "d3407" = 0 deg
sketch "スケッチ200"
  geometry: L1 (-13.25, 2)-(-13.25, 3.2) reference; L2 (-13.25, 3.2)-(-12.25, 3.2) reference; L3 (-12.25, 3.2)-(-12.25, 2) reference; L4 (-12.25, 2)-(-13.25, 2) reference; L5 (-13.25, 3.7)-(-13.25, 4.9) reference; L6 (-13.25, 4.9)-(-12.25, 4.9) reference; L7 (-12.25, 4.9)-(-12.25, 3.7) reference; L8 (-12.25, 3.7)-(-13.25, 3.7) reference; L9 (-13.25, 5.4)-(-13.25, 6.6) reference; L10 (-13.25, 6.6)-(-12.25, 6.6) reference; L11 (-12.25, 6.6)-(-12.25, 5.4) reference; L12 (-12.25, 5.4)-(-13.25, 5.4) reference; L13 (-11.75, 5.4)-(-11.75, 6.6) reference; L14 (-11.75, 6.6)-(-10.75, 6.6) reference; L15 (-10.75, 6.6)-(-10.75, 5.4) reference; L16 (-10.75, 5.4)-(-11.75, 5.4) reference; L17 (-11.75, 3.7)-(-11.75, 4.9) reference; L18 (-11.75, 4.9)-(-10.75, 4.9) reference; L19 (-10.75, 4.9)-(-10.75, 3.7) reference; L20 (-10.75, 3.7)-(-11.75, 3.7) reference; L21 (-11.75, 2)-(-11.75, 3.2) reference; L22 (-11.75, 3.2)-(-10.75, 3.2) reference; L23 (-10.75, 3.2)-(-10.75, 2) reference; L24 (-10.75, 2)-(-11.75, 2) reference; L25 (-14.5, 7)-(-14.5, 1) reference; L26 (-14.5, 1)-(-9.5, 1) reference; L27 (-14, 7.5)-(-10, 7.5); L28 (-10, 7.5)-(-10, 1.5); L29 (-10, 1.5)-(-14, 1.5); L30 (-14, 1.5)-(-14, 7.5); 1 further point
  constraints: 8 end point, 2 parallel, 1 horizontal, 1 perpendicular
  dimensions: "d3408" = 0.5 distance between parallel lines of L30 L25; "d3409" = 4 distance of L28.end L29.end; "d3410" = 0.5 distance between parallel lines of L26 L29; "d3411" = 6 distance of L27.end L28.end
extrude "押し出し189" cut sketch "スケッチ200" distance "d3412" = 0.5; taper "d3413" = 0 deg
sketch "スケッチ201"
  geometry: L1 (-16.25, 2)-(-16.25, 3.2) reference; L2 (-16.25, 3.2)-(-15.25, 3.2) reference; L3 (-15.25, 3.2)-(-15.25, 2) reference; L4 (-15.25, 2)-(-16.25, 2) reference; L5 (-17.75, 5.4)-(-17.75, 6.6) reference; L6 (-17.75, 6.6)-(-16.75, 6.6) reference; L7 (-16.75, 6.6)-(-16.75, 5.4) reference; L8 (-16.75, 5.4)-(-17.75, 5.4) reference; L9 (-15.25, 4.9)-(-15.25, 3.7) reference; L10 (-15.25, 3.7)-(-16.25, 3.7) reference; L11 (-16.25, 3.7)-(-16.25, 4.9) reference; L12 (-16.25, 4.9)-(-15.25, 4.9) reference; L13 (-16.75, 3.2)-(-16.75, 2) reference; L14 (-16.75, 2)-(-17.75, 2) reference; L15 (-17.75, 2)-(-17.75, 3.2) reference; L16 (-17.75, 3.2)-(-16.75, 3.2) reference; L17 (-17.75, 4.9)-(-16.75, 4.9) reference; L18 (-16.75, 4.9)-(-16.75, 3.7) reference; L19 (-16.75, 3.7)-(-17.75, 3.7) reference; L20 (-17.75, 3.7)-(-17.75, 4.9) reference; L21 (-16.25, 5.4)-(-16.25, 6.6) reference; L22 (-16.25, 6.6)-(-15.25, 6.6) reference; L23 (-15.25, 6.6)-(-15.25, 5.4) reference; L24 (-15.25, 5.4)-(-16.25, 5.4) reference; L25 (-19, 7)-(-19, 1) reference; L26 (-19, 1)-(-14, 1) reference; L27 (-18.5, 7.5)-(-14.5, 7.5); L28 (-14.5, 7.5)-(-14.5, 1.5); L29 (-14.5, 1.5)-(-18.5, 1.5); L30 (-18.5, 1.5)-(-18.5, 7.5); L31 (-6.5, 7.5)-(-2.5, 7.5); L32 (-2.5, 7.5)-(-2.5, 1.5); L33 (-2.5, 1.5)-(-6.5, 1.5); L34 (-6.5, 1.5)-(-6.5, 7.5); L35 (-7, 7)-(-7, 1) reference; 1 further point
  constraints: 16 end point, 4 parallel, 2 horizontal, 2 perpendicular
  dimensions: "d3414" = 0.5 distance between parallel lines of L26 L29; "d3415" = 4 distance of L28.end L29.end; "d3416" = 6 distance of L27.end L28.end; "d3417" = 4 distance of L32.end L33.end; "d3418" = 6 distance of L31.end L32.end; "d3419" = 0.5 distance between parallel lines of L30 L25; "d3420" = 0 distance between parallel lines of L29 L33; "d3421" = 0.5 distance between parallel lines of L34 L35
extrude "押し出し190" cut sketch "スケッチ201" distance "d3422" = 0.5; taper "d3423" = 0 deg
sketch "スケッチ202"
  geometry: L1 (13.25, 3.2)-(13.25, 2) reference; L2 (13.25, 2)-(12.25, 2) reference; L3 (12.25, 2)-(12.25, 3.2) reference; L4 (12.25, 3.2)-(13.25, 3.2) reference; L5 (13.25, 4.9)-(13.25, 3.7) reference; L6 (13.25, 3.7)-(12.25, 3.7) reference; L7 (12.25, 3.7)-(12.25, 4.9) reference; L8 (12.25, 4.9)-(13.25, 4.9) reference; L9 (13.25, 6.6)-(13.25, 5.4) reference; L10 (13.25, 5.4)-(12.25, 5.4) reference; L11 (12.25, 5.4)-(12.25, 6.6) reference; L12 (12.25, 6.6)-(13.25, 6.6) reference; L13 (11.75, 6.6)-(11.75, 5.4) reference; L14 (11.75, 5.4)-(10.75, 5.4) reference; L15 (10.75, 5.4)-(10.75, 6.6) reference; L16 (10.75, 6.6)-(11.75, 6.6) reference; L17 (11.75, 4.9)-(11.75, 3.7) reference; L18 (11.75, 3.7)-(10.75, 3.7) reference; L19 (10.75, 3.7)-(10.75, 4.9) reference; L20 (10.75, 4.9)-(11.75, 4.9) reference; L21 (11.75, 3.2)-(11.75, 2) reference; L22 (11.75, 2)-(10.75, 2) reference; L23 (10.75, 2)-(10.75, 3.2) reference; L24 (10.75, 3.2)-(11.75, 3.2) reference; L25 (9.5, 1)-(9.5, 7) reference; L26 (14.5, 1)-(9.5, 1) reference; L27 (10, 7.5)-(14, 7.5); L28 (14, 7.5)-(14, 1.5); L29 (14, 1.5)-(10, 1.5); L30 (10, 1.5)-(10, 7.5); 1 further point
  constraints: 8 end point, 2 parallel, 1 horizontal, 1 perpendicular
  dimensions: "d3424" = 4 distance of L28.end L29.end; "d3426" = 6 distance of L27.end L28.end; "d3427" = 0.5 distance between parallel lines of L26 L29; "d3428" = 0.5 distance between parallel lines of L30 L25
extrude "押し出し191" cut sketch "スケッチ202" distance "d3429" = 0.5; taper "d3430" = 0 deg
sketch "スケッチ203"
  geometry: L1 (3.25, 6.6)-(4.25, 6.6) reference; L2 (4.25, 6.6)-(4.25, 5.4) reference; L3 (4.25, 5.4)-(3.25, 5.4) reference; L4 (3.25, 5.4)-(3.25, 6.6) reference; L5 (5.75, 3.2)-(5.75, 2) reference; L6 (5.75, 2)-(4.75, 2) reference; L7 (4.75, 2)-(4.75, 3.2) reference; L8 (4.75, 3.2)-(5.75, 3.2) reference; L9 (3.25, 3.7)-(3.25, 4.9) reference; L10 (3.25, 4.9)-(4.25, 4.9) reference; L11 (4.25, 4.9)-(4.25, 3.7) reference; L12 (4.25, 3.7)-(3.25, 3.7) reference; L13 (4.75, 4.9)-(5.75, 4.9) reference; L14 (5.75, 4.9)-(5.75, 3.7) reference; L15 (5.75, 3.7)-(4.75, 3.7) reference; L16 (4.75, 3.7)-(4.75, 4.9) reference; L17 (4.25, 3.2)-(4.25, 2) reference; L18 (4.25, 2)-(3.25, 2) reference; L19 (3.25, 2)-(3.25, 3.2) reference; L20 (3.25, 3.2)-(4.25, 3.2) reference; L21 (4.75, 6.614)-(5.75, 6.614) reference; L22 (5.75, 6.614)-(5.75, 5.4) reference; L23 (5.75, 5.4)-(4.75, 5.4) reference; L24 (4.75, 5.4)-(4.75, 6.614) reference; L25 (7, 1)-(2, 1) reference; L26 (7, 7)-(7, 1) reference; L27 (2.5, 7.5)-(6.5, 7.5); L28 (6.5, 7.5)-(6.5, 1.5); L29 (6.5, 1.5)-(2.5, 1.5); L30 (2.5, 1.5)-(2.5, 7.5); L31 (14.5, 7.5)-(18.5, 7.5); L32 (18.5, 7.5)-(18.5, 1.5); L33 (18.5, 1.5)-(14.5, 1.5); L34 (14.5, 1.5)-(14.5, 7.5); L35 (14, 1)-(14, 7) reference; 1 further point
  constraints: 16 end point, 4 parallel, 2 horizontal, 2 perpendicular
  dimensions: "d3431" = 4 distance of L28.end L29.end; "d3433" = 6 distance of L29.end L27.start; "d3434" = 0 distance between parallel lines of L31 L27; "d3435" = 0 distance between parallel lines of L29 L33; "d3436" = 4 distance of L31.start L31.end; "d3437" = 0.5 distance between parallel lines of L26 L28; "d3438" = 0.5 distance between parallel lines of L25 L29; "d3439" = 0.5 distance between parallel lines of L34 L35
extrude "押し出し192" cut sketch "スケッチ203" distance "d3440" = 0.5; taper "d3441" = 0 deg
